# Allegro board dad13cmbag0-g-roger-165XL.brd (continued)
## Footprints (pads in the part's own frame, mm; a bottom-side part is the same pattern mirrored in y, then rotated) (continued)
BGA128-ITE-IT8528VGAX
  round 0.254 smd: A1(-3,3) A2(-2.5,3) A3(-2,3) A4(-1.5,3) A5(-1,3) A6(-0.5,3) A7(0,3) A8(0.5,3) A9(1,3) A10(1.5,3) A11(2,3) A12(2.5,3) A13(3,3) B1(-3,2.5) B2(-2.5,2.5) B3(-2,2.5) B4(-1.5,2.5) B5(-1,2.5) B6(-0.5,2.5) B7(0,2.5) B8(0.5,2.5) B9(1,2.5) B10(1.5,2.5) B11(2,2.5) B12(2.5,2.5) B13(3,2.5) C1(-3,2) C2(-2.5,2) C12(2.5,2) C13(3,2) D1(-3,1.5) D2(-2.5,1.5) D4(-1.5,1.5) D5(-1,1.5) D6(-0.5,1.5) D7(0,1.5) D8(0.5,1.5) D9(1,1.5) D10(1.5,1.5) D12(2.5,1.5) D13(3,1.5) E1(-3,1) E2(-2.5,1) E4(-1.5,1) E5(-1,1) E6(-0.5,1) E7(0,1) E8(0.5,1) E9(1,1) E10(1.5,1) E12(2.5,1) E13(3,1) F1(-3,0.5) F2(-2.5,0.5) F4(-1.5,0.5) F5(-1,0.5) F9(1,0.5) F10(1.5,0.5) F12(2.5,0.5) F13(3,0.5) G1(-3,0) G2(-2.5,0) G4(-1.5,0) G5(-1,0) G9(1,0) G10(1.5,0) G12(2.5,0) G13(3,0) H1(-3,-0.5) H2(-2.5,-0.5) H4(-1.5,-0.5) H5(-1,-0.5) H9(1,-0.5) H10(1.5,-0.5) H12(2.5,-0.5) H13(3,-0.5) J1(-3,-1) J2(-2.5,-1) J4(-1.5,-1) J5(-1,-1) J6(-0.5,-1) J7(0,-1) J8(0.5,-1) J9(1,-1) J10(1.5,-1) J12(2.5,-1) J13(3,-1) K1(-3,-1.5) K2(-2.5,-1.5) K4(-1.5,-1.5) K5(-1,-1.5) K6(-0.5,-1.5) K7(0,-1.5) K8(0.5,-1.5) K9(1,-1.5) K10(1.5,-1.5) K12(2.5,-1.5) K13(3,-1.5) L1(-3,-2) L2(-2.5,-2) L12(2.5,-2) L13(3,-2) M1(-3,-2.5) M2(-2.5,-2.5) M3(-2,-2.5) M4(-1.5,-2.5) M5(-1,-2.5) M6(-0.5,-2.5) M7(0,-2.5) M8(0.5,-2.5) M9(1,-2.5) M10(1.5,-2.5) M11(2,-2.5) M12(2.5,-2.5) M13(3,-2.5) N1(-3,-3) N2(-2.5,-3) N3(-2,-3) N4(-1.5,-3) N5(-1,-3) N6(-0.5,-3) N7(0,-3) N8(0.5,-3) N9(1,-3) N10(1.5,-3) N11(2,-3) N12(2.5,-3) N13(3,-3)
BGA1168-INTEL-HASWELL
  round 0.508 smd: A3(18.177,-11.314) A62(-18.722,-11.314) AW1(19.314,10.727) AW63(-19.314,10.743) AY2(18.771,11.314) AY62(-18.748,11.314) B2(18.806,-10.806) B63(-19.314,-10.722) C1(19.314,-10.177)
  round 0.381 smd: A4(17.421,-11.314) A5(16.76,-11.314) A6(15.564,-11.314) A59(-16.586,-11.314) A60(-17.412,-11.314) A61(-18.072,-11.314) AA9(14.282,0.262) AA21(7.627,0.175) AA23(6.199,0.175) AA58(-16.063,0.015) AB10(13.838,0.738) AB20(8.135,0.582) AB21(7.627,0.988) AB22(6.707,0.582) AB23(6.199,0.988) AB57(-15.743,0.666) AC9(14.282,1.215) AC20(8.135,1.394) AC22(6.707,1.394) AC58(-16.063,1.316) AD10(13.838,1.691) AD21(7.627,1.801) AD23(6.199,1.801) AD57(-15.743,1.966) AE9(14.282,2.167) AE10(13.838,2.643) AE20(8.135,2.207) AE21(7.627,2.614) AE22(6.707,2.207) AE23(6.199,2.614) AE58(-16.063,2.616) AF9(14.282,3.12) AF11(13.255,2.968) AF12(12.442,2.968) AF14(11.63,2.968) AF15(10.817,2.968) AF17(10.004,2.968) AF18(9.191,2.968) AF20(8.378,2.968) AF22(6.707,3.02) AG10(13.662,3.476) AG11(12.849,3.476) AG13(12.036,3.476) AG14(11.223,3.476) AG16(10.41,3.476) AG17(9.598,3.476) AG19(8.785,3.476) AG20(7.972,3.476) AG23(6.199,3.426) AG57(-15.743,3.267) AG58(-16.377,3.695) AH22(6.707,3.833) AH24(5.394,3.975) AH26(4.094,3.975) AH28(2.793,3.975) AH30(1.493,3.975) AH32(0.192,3.975) AH34(-1.108,3.975) AH36(-2.409,3.975) AH38(-3.709,3.975) AH40(-5.01,3.975) AH42(-6.31,3.975) AH44(-7.611,3.975) AH46(-8.911,3.975) AH49(-10.212,3.975) AH51(-11.512,3.975) AH53(-12.813,3.975) AH55(-14.113,3.975) AH57(-15.413,3.975) AJ23(6.199,4.239) AJ25(4.744,4.3) AJ27(3.443,4.3) AJ29(2.143,4.3) AJ31(0.843,4.3) AJ33(-0.458,4.3) AJ35(-1.758,4.3) AJ37(-3.059,4.3) AJ39(-4.359,4.3) AJ41(-5.66,4.3) AJ43(-6.96,4.3) AJ45(-8.261,4.3) AJ47(-9.561,4.3) AJ50(-10.862,4.3) AJ52(-12.162,4.3) AJ54(-13.463,4.3) AJ56(-14.763,4.3) AJ58(-16.064,4.3) AT1(19.314,8.683) AT63(-19.314,8.533) AU1(19.314,9.343) AU63(-19.314,9.359) AV1(19.314,10.004) AV2(18.654,9.993) AV62(-18.664,10.004) AV63(-19.314,10.019) AW2(18.654,10.654) AW3(17.993,10.654) AW61(-18.014,10.664) AW62(-18.664,10.664) AY3(18.047,11.314) AY4(17.387,11.314) AY5(16.726,11.314) AY59(-16.774,11.314) AY60(-17.434,11.314) AY61(-18.095,11.314) B3(18.056,-10.664) B61(-18.001,-10.654) B62(-18.664,-10.59) C2(18.664,-10.056) C62(-18.664,-9.93) C63(-19.314,-9.998) D1(19.314,-9.453) D63(-19.314,-9.338) E1(19.314,-8.792) E23(5.981,-8.713) E25(4.6,-8.713) E27(3.474,-8.713) E29(2.093,-8.713) E31(0.966,-8.713) E33(-0.415,-8.713) E35(-1.541,-8.713) E37(-2.922,-8.713) E39(-4.049,-8.713) E41(-5.43,-8.713) E43(-6.556,-8.713) E45(-7.937,-8.713) E47(-9.064,-8.713) E49(-10.444,-8.713) E51(-11.571,-8.713) E53(-12.952,-8.713) E55(-14.079,-8.713) E57(-15.459,-8.713) E63(-19.314,-8.667) F1(19.314,-7.878) F22(6.597,-8.256) F24(5.291,-8.188) F26(4.037,-8.188) F28(2.783,-8.188) F30(1.53,-8.188) F32(0.276,-8.188) F34(-0.978,-8.188) F36(-2.232,-8.188) F38(-3.485,-8.188) F40(-4.739,-8.188) F42(-5.993,-8.188) F44(-7.247,-8.188) F46(-8.5,-8.188) F48(-9.754,-8.188) F50(-11.008,-8.188) F52(-12.262,-8.188) F54(-13.515,-8.188) F56(-14.769,-8.188) F58(-16.063,-8.188) G22(6.707,-7.546) G23(5.981,-7.863) G25(4.6,-7.863) G27(3.474,-7.863) G29(2.093,-7.863) G31(0.966,-7.863) G33(-0.415,-7.863) G35(-1.541,-7.863) G37(-2.922,-7.863) G39(-4.049,-7.863) G41(-5.43,-7.863) G43(-6.556,-7.863) G45(-7.937,-7.863) G47(-9.064,-7.863) G49(-10.444,-7.863) G51(-11.571,-7.863) G53(-12.952,-7.863) G55(-14.079,-7.863) G57(-15.459,-7.863) H22(6.707,-6.734) H23(6.199,-7.14) H57(-15.743,-7.213) J22(6.707,-5.921) J23(6.199,-6.327) J58(-16.063,-6.487) K9(14.282,-5.453) K10(13.379,-5.614) K12(12.426,-5.614) K14(11.474,-5.614) K16(10.521,-5.614) K18(9.569,-5.614) K19(8.616,-5.614) K21(7.664,-5.614) K23(6.199,-5.514) K57(-15.743,-5.837) L10(13.838,-4.977) L11(12.902,-5.17) L13(11.95,-5.17) L15(10.997,-5.17) L17(10.045,-5.17) L18(9.092,-5.17) L20(8.135,-5.108) L22(6.707,-5.108) L58(-16.063,-5.186) M9(14.282,-4.5) M20(8.135,-4.295) M21(7.627,-4.702) M22(6.707,-4.295) M23(6.199,-4.702) M57(-15.743,-4.536) N10(13.838,-4.024) N21(7.627,-3.889) N23(6.199,-3.889) N58(-16.063,-3.886) P9(14.282,-3.548) P20(8.135,-3.482) P22(6.707,-3.482) P57(-15.743,-3.236) R10(13.838,-3.072) R20(8.135,-2.67) R21(7.627,-3.076) R22(6.707,-2.67) R23(6.199,-3.076) T9(14.282,-2.595) T21(7.627,-2.263) T23(6.199,-2.263) T58(-16.063,-2.585) U9(14.282,-1.643) U10(13.838,-2.119) U20(8.135,-1.857) U22(6.707,-1.857) U57(-15.743,-1.935) V10(13.838,-1.167) V21(7.627,-1.45) V23(6.199,-1.45) V58(-16.063,-1.285) W9(14.282,-0.69) W20(8.135,-1.044) W21(7.627,-0.638) W22(6.707,-1.044) W23(6.199,-0.638) W57(-15.743,-0.635) Y10(13.838,-0.214) Y20(8.135,-0.231) Y22(6.707,-0.231)
  round 0.305 smd: A8(14.776,-11.314) A9(13.862,-11.314) A11(12.948,-11.314) A12(12.198,-11.314) A14(11.284,-11.314) A15(10.37,-11.314) A17(9.62,-11.314) A18(8.706,-11.314) A20(7.791,-11.314) A21(7.042,-11.314) A23(6.128,-11.314) A24(5.291,-10.989) A25(4.6,-11.314) A27(3.474,-11.314) A28(2.783,-10.989) A29(2.093,-11.314) A31(0.966,-11.314) A32(0.276,-10.989) A33(-0.415,-11.314) A35(-1.541,-11.314) A36(-2.232,-10.989) A37(-2.922,-11.314) A39(-4.049,-11.314) A40(-4.739,-10.989) A41(-5.43,-11.314) A43(-6.556,-11.314) A44(-7.247,-10.989) A45(-7.937,-11.314) A47(-9.064,-11.314) A48(-9.754,-10.989) A49(-10.444,-11.314) A51(-11.571,-11.314) A52(-12.262,-10.989) A53(-12.952,-11.314) A55(-14.079,-11.314) A56(-14.769,-10.989) A57(-15.459,-11.314) AA1(19.314,0.402) AA2(18.664,0.402) AA3(18.014,0.364) AA4(17.363,0.364) AA59(-16.713,0.324) AA60(-17.363,0.324) AA61(-18.014,0.324) AA62(-18.664,0.362) AA63(-19.314,0.362) AB5(16.678,0.738) AB6(16.027,0.738) AB7(15.377,0.738) AB8(14.727,0.738) AC1(19.314,1.152) AC2(18.664,1.152) AC3(18.014,1.19) AC4(17.363,1.19) AC59(-16.713,1.15) AC60(-17.363,1.15) AC61(-18.014,1.15) AC62(-18.664,1.112) AC63(-19.314,1.112) AD1(19.314,1.901) AD2(18.664,1.901) AD3(18.014,1.863) AD4(17.363,1.863) AD5(16.678,1.691) AD6(16.027,1.691) AD7(15.377,1.691) AD8(14.727,1.691) AD59(-16.713,1.823) AD60(-17.363,1.823) AD61(-18.014,1.823) AD62(-18.664,1.861) AD63(-19.314,1.861) AE5(16.678,2.643) AE6(16.027,2.643) AE7(15.377,2.643) AE8(14.727,2.643) AE59(-16.713,2.648) AE60(-17.363,2.648) AE61(-18.014,2.648) AE62(-18.664,2.61) AE63(-19.314,2.61) AF1(19.314,2.65) AF2(18.664,2.65) AF3(18.014,2.688) AF4(17.363,2.688) AG1(19.314,3.4) AG2(18.664,3.4) AG3(18.014,3.361) AG4(17.363,3.361) AG5(16.678,3.596) AG6(16.027,3.596) AG7(15.377,3.596) AG8(14.727,3.596) AG21(7.359,3.807) AG60(-17.038,3.288) AG61(-17.689,3.288) AG62(-18.339,3.288) AG63(-18.989,3.288) AH1(19.314,4.149) AH2(18.664,4.149) AH3(18.014,4.187) AH4(17.363,4.187) AH10(13.662,4.162) AH11(12.849,4.162) AH13(12.036,4.162) AH14(11.223,4.162) AH16(10.41,4.162) AH17(9.598,4.162) AH19(8.785,4.162) AH20(7.972,4.162) AH60(-17.363,3.964) AH61(-18.014,3.964) AH62(-18.664,3.964) AH63(-19.314,3.964) AJ5(16.678,4.548) AJ6(16.027,4.548) AJ7(15.377,4.548) AJ8(14.727,4.548) AJ10(13.662,4.812) AJ11(12.849,4.812) AJ13(12.036,4.812) AJ14(11.223,4.812) AJ60(-17.038,4.64) AJ61(-17.689,4.64) AJ62(-18.339,4.64) AJ63(-18.989,4.64) AK1(19.314,4.898) AK2(18.664,4.898) AK3(18.014,4.86) AK4(17.363,4.86) AK8(15.011,5.137) AK18(9.466,4.952) AK20(8.513,4.952) AK21(7.561,4.952) AK60(-17.363,5.209) AK61(-18.014,5.209) AK62(-18.664,5.315) AK63(-19.314,5.315) AL1(19.314,5.647) AL2(18.664,5.647) AL3(18.014,5.686) AL4(17.363,5.686) AL5(16.413,5.462) AL7(15.575,5.462) AL8(15.011,5.787) AL10(13.657,5.462) AL11(13.093,5.787) AL13(11.738,5.462) AL15(11.174,5.787) AL17(10.092,5.268) AL18(9.466,5.602) AL20(8.513,5.602) AL21(7.561,5.602) AL22(6.608,5.602) AL23(5.786,5.602) AL25(4.81,5.602) AL26(3.858,5.602) AL28(2.905,5.602) AL29(1.953,5.602) AL31(1.054,5.277) AL32(0.49,5.602) AL33(-0.412,5.602) AL35(-1.415,5.602) AL36(-2.266,5.602) AL38(-3.32,5.602) AL39(-4.228,5.277) AL40(-4.817,5.602) AL42(-5.63,5.602) AL43(-6.582,5.602) AL45(-7.56,5.602) AL46(-8.487,5.602) AL48(-9.542,5.602) AL49(-10.443,5.602) AL51(-11.447,5.602) AL52(-12.269,5.602) AL54(-13.295,5.602) AL55(-14.248,5.602) AL57(-15.195,5.602) AL58(-16.094,5.602) AL60(-17.038,5.855) AL61(-17.689,5.855) AM1(19.314,6.397) AM2(18.664,6.397) AM3(18.014,6.359) AM4(17.363,6.359) AM5(16.413,6.112) AM7(15.575,6.112) AM8(15.011,6.437) AM10(13.657,6.112) AM11(13.093,6.437) AM13(11.738,6.112) AM15(11.174,6.437) AM17(10.092,5.919) AM18(9.466,6.252) AM20(8.513,6.252) AM21(7.561,6.252) AM22(6.608,6.252) AM23(5.786,6.252) AM25(4.81,6.252) AM26(3.858,6.252) AM28(2.905,6.252) AM29(1.953,6.252) AM31(1.054,5.927) AM32(0.49,6.252) AM33(-0.412,6.252) AM35(-1.415,6.252) AM36(-2.266,6.252) AM38(-3.32,6.252) AM40(-4.817,6.252) AM42(-5.63,6.252) AM43(-6.582,6.252) AM45(-7.56,6.252) AM46(-8.487,6.252) AM48(-9.542,6.252) AM49(-10.443,6.252) AM51(-11.447,6.252) AM52(-12.269,6.252) AM54(-13.295,6.252) AM55(-14.248,6.252) AM57(-15.195,6.252) AM58(-16.094,6.252) AM60(-17.363,6.501) AM61(-18.014,6.501) AM62(-18.664,6.395) AM63(-19.314,6.395) AN1(19.314,7.146) AN2(18.664,7.146) AN3(18.014,7.184) AN4(17.363,7.184) AN5(16.413,6.762) AN7(15.575,6.762) AN8(15.011,7.088) AN10(13.657,6.762) AN11(13.093,7.088) AN13(11.738,6.762) AN15(11.174,7.088) AN17(10.092,6.569) AN18(9.466,6.903) AN20(8.513,6.903) AN21(7.561,6.903) AN22(6.608,6.903) AN23(5.786,6.903) AN25(4.81,6.903) AN26(3.858,6.903) AN28(2.905,6.903) AN29(1.953,6.903) AN31(1.054,6.578) AN32(0.49,6.903) AN33(-0.412,6.903) AN35(-1.415,6.903) AN36(-2.266,6.903) AN38(-3.32,6.903) AN39(-4.228,6.578) AN40(-4.817,6.903) AN42(-5.63,6.903) AN43(-6.582,6.903) AN45(-7.56,6.903) AN46(-8.487,6.903) AN48(-9.542,6.903) AN49(-10.443,6.903) AN51(-11.447,6.903) AN52(-12.269,6.903) AN54(-13.295,6.903) AN55(-14.248,6.903) AN57(-15.195,6.903) AN58(-16.094,6.903) AN60(-17.038,7.07) AN61(-17.689,7.07) AN62(-18.339,7.07) AN63(-18.989,7.07) AP1(19.314,7.895) AP2(18.664,7.895) AP3(18.014,7.857) AP4(17.363,7.857) AP5(16.413,7.413) AP7(15.575,7.413) AP8(15.011,7.738) AP10(13.657,7.413) AP11(13.093,7.738) AP13(11.738,7.413) AP15(11.174,7.738) AP17(10.092,7.219) AP18(9.466,7.553) AP20(8.513,7.553) AP21(7.561,7.553) AP22(6.608,7.553) AP23(5.786,7.553) AP25(4.81,7.553) AP26(3.858,7.553) AP28(2.905,7.553) AP29(1.953,7.553) AP31(1.054,7.228) AP32(0.49,7.553) AP33(-0.412,7.553) AP35(-1.415,7.553) AP36(-2.266,7.553) AP38(-3.32,7.553) AP39(-4.228,7.228) AP40(-4.817,7.553) AP42(-5.63,7.553) AP43(-6.582,7.553) AP45(-7.56,7.553) AP46(-8.487,7.553) AP48(-9.542,7.553) AP49(-10.443,7.553) AP51(-11.447,7.553) AP52(-12.269,7.553) AP54(-13.295,7.553) AP55(-14.248,7.553) AP57(-15.195,7.553) AP58(-16.094,7.553) AP60(-17.363,7.746) AP61(-18.014,7.746) AP62(-18.664,7.746) AP63(-19.314,7.746) AR5(16.413,8.063) AR7(15.575,8.063) AR8(15.011,8.388) AR10(13.657,8.063) AR11(13.093,8.388) AR13(11.738,8.063) AR15(11.174,8.388) AR17(10.092,7.869) AR18(9.466,8.203) AR20(8.513,8.203) AR21(7.561,8.203) AR22(6.608,8.203) AR23(5.786,8.203) AR25(4.81,8.203) AR26(3.858,8.203) AR28(2.905,8.203) AR29(1.953,8.203) AR31(1.054,7.878) AR32(0.49,8.203) AR33(-0.412,8.203) AR35(-1.415,8.203) AR36(-2.266,8.203) AR38(-3.32,8.203) AR39(-4.228,7.878) AR40(-4.817,8.203) AR42(-5.63,8.203) AR43(-6.582,8.203) AR45(-7.56,8.203) AR46(-8.487,8.203) AR48(-9.542,8.203) AR49(-10.443,8.203) AR51(-11.447,8.203) AR52(-12.269,8.203) AR54(-13.295,8.203) AR55(-14.248,8.203) AR57(-15.195,8.203) AR58(-16.094,8.203) AT2(18.664,8.645) AT3(18.014,8.683) AT4(17.363,8.683) AT5(16.413,8.713) AT7(15.575,8.713) AT10(13.657,8.713) AT13(11.738,8.713) AT35(-1.122,8.905) AT37(-2.697,8.905) AT40(-4.272,8.905) AT42(-5.847,8.905) AT43(-7.422,8.905) AT46(-8.996,8.905) AT49(-10.597,8.933) AT61(-17.689,8.32) AT62(-18.498,8.376) AU2(18.659,9.333) AU3(17.999,9.333) AU4(17.338,9.333) AU6(15.977,9.363) AU7(15.151,9.363) AU8(14.478,9.363) AU10(13.653,9.363) AU11(12.98,9.363) AU12(12.154,9.363) AU14(11.481,9.363) AU15(10.656,9.363) AU16(10.092,9.038) AU17(9.454,9.363) AU18(8.778,9.038) AU19(8.21,9.363) AU20(7.563,9.038) AU21(6.917,9.363) AU22(6.348,9.038) AU23(5.672,9.363) AU24(4.996,9.038) AU25(4.321,9.363) AU26(3.645,9.038) AU27(3.076,9.363) AU28(2.43,9.038) AU29(1.783,9.363) AU30(1.214,9.038) AU31(0.539,9.363) AU33(-0.058,9.016) AU34(-0.66,9.363) AU35(-1.585,9.363) AU36(-2.235,9.363) AU37(-3.16,9.363) AU39(-3.81,9.363) AU40(-4.734,9.363) AU41(-5.385,9.363) AU42(-6.309,9.363) AU43(-6.959,9.363) AU44(-7.884,9.363) AU46(-8.534,9.363) AU47(-9.459,9.363) AU49(-10.109,9.363) AU50(-11.086,9.363) AU51(-11.666,9.038) AU52(-12.342,9.363) AU53(-13.017,9.038) AU54(-13.586,9.363) AU55(-14.233,9.038) AU56(-14.879,9.363) AU57(-15.448,9.038) AU58(-16.124,9.363) AU59(-16.688,9.038) AU60(-17.251,9.363) AU61(-17.963,9.087) AU62(-18.664,9.349) AV3(17.993,9.993) AV4(17.338,9.993) AV5(16.65,10.014) AV6(15.977,10.014) AV7(15.151,10.014) AV8(14.478,10.014) AV10(13.653,10.014) AV11(12.98,10.014) AV12(12.154,10.014) AV14(11.481,10.014) AV15(10.656,10.014) AV16(10.092,9.689) AV17(9.454,10.014) AV18(8.778,9.689) AV19(8.21,10.014) AV20(7.563,9.689) AV21(6.917,10.014) AV22(6.348,9.689) AV23(5.672,10.014) AV24(4.996,9.689) AV25(4.321,10.014) AV26(3.645,9.689) AV27(3.076,10.014) AV28(2.43,9.689) AV29(1.783,10.014) AV30(1.214,9.689) AV31(0.539,10.014) AV33(-0.086,9.689) AV34(-0.71,10.014) AV35(-1.535,10.014) AV36(-2.284,10.014) AV37(-3.11,10.014) AV39(-3.859,10.014) AV40(-4.685,10.014) AV41(-5.434,10.014) AV42(-6.26,10.014) AV43(-7.009,10.014) AV44(-7.834,10.014) AV46(-8.584,10.014) AV47(-9.409,10.014) AV49(-10.158,10.014) AV50(-10.984,10.014) AV51(-11.666,9.689) AV52(-12.342,10.014) AV53(-13.017,9.689) AV54(-13.586,10.014) AV55(-14.233,9.689) AV56(-14.879,10.014) AV57(-15.448,9.689) AV58(-16.124,10.014) AV59(-16.688,9.689) AV60(-17.251,10.014) AV61(-17.988,9.737) AW4(17.338,10.654) AW5(16.688,10.664) AW6(15.939,10.664) AW7(15.189,10.664) AW8(14.44,10.664) AW10(13.691,10.664) AW11(12.942,10.664) AW12(12.192,10.664) AW14(11.443,10.664) AW15(10.694,10.664) AW16(10.092,10.339) AW17(9.454,10.664) AW18(8.778,10.339) AW19(8.103,10.664) AW21(7.023,10.664) AW22(6.348,10.339) AW23(5.672,10.664) AW24(4.996,10.339) AW25(4.321,10.664) AW26(3.645,10.339) AW27(2.97,10.664) AW29(1.89,10.664) AW30(1.214,10.339) AW31(0.539,10.664) AW33(-0.137,10.339) AW34(-0.71,10.664) AW35(-1.535,10.664) AW36(-2.284,10.664) AW37(-3.11,10.664) AW39(-3.859,10.664) AW40(-4.685,10.664) AW41(-5.434,10.664) AW42(-6.26,10.664) AW43(-7.009,10.664) AW44(-7.834,10.664) AW46(-8.584,10.664) AW47(-9.409,10.664) AW49(-10.158,10.664) AW50(-10.984,10.664) AW51(-11.666,10.339) AW52(-12.342,10.664) AW53(-13.017,10.339) AW54(-13.693,10.664) AW56(-14.772,10.664) AW57(-15.448,10.339) AW58(-16.124,10.664) AW59(-16.688,10.339) AW60(-17.251,10.664) AY6(15.939,11.314) AY7(15.189,11.314) AY8(14.44,11.314) AY10(13.691,11.314) AY11(12.942,11.314) AY12(12.192,11.314) AY14(11.443,11.314) AY15(10.694,11.314) AY16(10.13,10.989) AY17(9.454,11.314) AY18(8.778,10.989) AY19(8.103,11.314) AY21(7.023,11.314) AY22(6.348,10.989) AY23(5.672,11.314) AY24(4.996,10.989) AY25(4.321,11.314) AY26(3.645,10.989) AY27(2.97,11.314) AY29(1.89,11.314) AY30(1.214,10.989) AY31(0.539,11.314) AY33(-0.137,10.989) AY34(-0.71,11.314) AY35(-1.535,11.314) AY36(-2.284,11.314) AY37(-3.11,11.314) AY39(-3.859,11.314) AY40(-4.685,11.314) AY41(-5.434,11.314) AY42(-6.26,11.314) AY43(-7.009,11.314) AY44(-7.834,11.314) AY46(-8.584,11.314) AY47(-9.409,11.314) AY49(-10.158,11.314) AY50(-10.984,11.314) AY51(-11.666,10.989) AY52(-12.342,11.314) AY53(-13.017,10.989) AY54(-13.693,11.314) AY56(-14.772,11.314) AY57(-15.448,10.989) AY58(-16.124,11.314) B4(17.393,-10.664) B5(16.176,-10.672) B6(15.196,-10.672) B8(14.423,-10.672) B9(13.598,-10.672) B11(12.617,-10.672) B12(11.845,-10.672) B14(11.02,-10.672) B15(10.039,-10.672) B17(9.267,-10.672) B18(8.442,-10.672) B20(7.461,-10.672) B21(7.042,-10.118) B22(6.689,-10.672) B23(5.864,-10.672) B24(5.291,-10.339) B25(4.6,-10.664) B26(4.037,-10.339) B27(3.474,-10.664) B28(2.783,-10.339) B29(2.093,-10.664) B30(1.53,-10.339) B31(0.966,-10.664) B32(0.276,-10.339) B33(-0.415,-10.664) B34(-0.978,-10.339) B35(-1.541,-10.664) B36(-2.232,-10.339) B37(-2.922,-10.664) B38(-3.485,-10.339) B39(-4.049,-10.664) B40(-4.739,-10.339) B41(-5.43,-10.664) B42(-5.993,-10.339) B43(-6.556,-10.664) B44(-7.247,-10.339) B45(-7.937,-10.664) B46(-8.5,-10.339) B47(-9.064,-10.664) B48(-9.754,-10.339) B49(-10.444,-10.664) B50(-11.008,-10.339) B51(-11.571,-10.664) B52(-12.262,-10.339) B53(-12.952,-10.664) B54(-13.515,-10.339) B55(-14.079,-10.664) B56(-14.769,-10.339) B57(-15.459,-10.664) B58(-16.023,-10.339) B59(-16.586,-10.664) B60(-17.351,-10.654) C3(18.012,-10.012) C4(17.196,-10.042) C5(16.542,-10.118) C6(15.538,-10.118) C8(14.776,-10.118) C9(13.964,-10.118) C11(12.96,-10.118) C12(12.198,-10.118) C14(11.386,-10.118) C15(10.382,-10.118) C17(9.62,-10.118) C18(8.807,-10.118) C20(7.804,-10.118) C21(7.423,-9.529) C22(6.636,-9.529) C23(6.229,-10.118) C24(5.263,-9.282) C25(4.6,-10.014) C26(4.037,-9.689) C27(3.474,-10.014) C28(2.756,-9.282) C29(2.093,-10.014) C30(1.53,-9.689) C31(0.966,-10.014) C32(0.248,-9.282) C33(-0.415,-10.014) C34(-0.978,-9.689) C35(-1.541,-10.014) C36(-2.259,-9.282) C37(-2.922,-10.014) C38(-3.485,-9.689) C39(-4.049,-10.014) C40(-4.767,-9.282) C41(-5.43,-10.014) C42(-5.993,-9.689) C43(-6.556,-10.014) C44(-7.274,-9.282) C45(-7.937,-10.014) C46(-8.5,-9.689) C47(-9.064,-10.014) C48(-9.756,-9.282) C49(-10.444,-10.014) C50(-11.008,-9.689) C51(-11.571,-10.014) C52(-12.264,-9.323) C53(-12.952,-10.014) C54(-13.515,-9.689) C55(-14.079,-10.014) C56(-14.771,-9.323) C57(-15.459,-10.014) C58(-16.023,-9.689) C59(-16.586,-10.014) C61(-17.689,-10.077) D2(18.664,-9.24) D3(18.014,-9.278) D5(16.636,-9.472) D6(15.945,-9.529) D8(15.157,-9.529) D9(14.37,-9.529) D11(13.462,-9.529) D12(12.579,-9.529) D14(11.792,-9.529) D15(10.884,-9.529) D17(10.001,-9.529) D18(9.214,-9.529) D20(8.306,-9.529) D21(7.079,-8.891) D23(5.937,-9.529) D25(4.6,-9.363) D26(4.037,-9.038) D27(3.474,-9.363) D29(2.093,-9.363) D30(1.53,-9.038) D31(0.966,-9.363) D33(-0.415,-9.363) D34(-0.978,-9.038) D35(-1.541,-9.363) D37(-2.922,-9.363) D38(-3.485,-9.038) D39(-4.049,-9.363) D41(-5.43,-9.363) D42(-5.993,-9.038) D43(-6.556,-9.363) D45(-7.937,-9.363) D46(-8.5,-9.038) D47(-9.064,-9.363) D49(-10.444,-9.363) D50(-11.008,-9.038) D51(-11.571,-9.363) D53(-12.952,-9.363) D54(-13.515,-9.038) D55(-14.079,-9.363) D57(-15.459,-9.363) D58(-16.023,-9.038) D59(-16.586,-9.363) D60(-17.363,-9.513) D61(-18.014,-9.513) D62(-18.664,-9.28) E2(18.664,-8.589) E3(18.014,-8.627) E4(17.363,-8.627) E5(16.712,-8.695) E6(15.76,-8.695) E8(14.807,-8.695) E10(13.855,-8.695) E11(12.902,-8.695) E13(11.95,-8.695) E15(10.997,-8.695) E17(10.045,-8.695) E18(9.092,-8.695) E20(8.14,-8.695) E59(-16.713,-8.667) E60(-17.363,-8.667) E61(-18.014,-8.667) E62(-18.664,-8.629) F2(18.664,-7.84) F3(18.014,-7.802) F4(17.363,-7.802) F5(16.712,-8.045) F6(15.76,-8.045) F8(14.807,-8.045) F10(13.855,-8.045) F11(12.902,-8.045) F13(11.95,-8.045) F15(10.997,-8.045) F17(10.045,-8.045) F18(9.092,-8.045) F20(8.14,-8.045) F59(-16.713,-7.842) F60(-17.363,-7.842) F61(-18.014,-7.842) F62(-18.664,-7.88) F63(-19.314,-7.88) G1(19.314,-7.091) G2(18.664,-7.091) G3(18.014,-7.129) G4(17.363,-7.129) G5(16.712,-7.395) G6(15.76,-7.395) G8(14.807,-7.395) G10(13.855,-7.395) G11(12.902,-7.395) G13(11.95,-7.395) G15(10.997,-7.395) G17(10.045,-7.395) G18(9.092,-7.395) G20(8.14,-7.395) H5(16.712,-6.745) H6(15.76,-6.745) H8(14.807,-6.745) H10(13.855,-6.745) H11(12.902,-6.745) H13(11.95,-6.745) H15(10.997,-6.745) H17(10.045,-6.745) H18(9.092,-6.745) H20(8.14,-6.745) H59(-16.713,-7.169) H60(-17.363,-7.169) H61(-18.014,-7.169) H62(-18.664,-7.131) H63(-19.314,-7.131) J1(19.314,-6.341) J2(18.664,-6.341) J3(18.014,-6.303) J4(17.363,-6.303) J5(16.687,-6.094) J6(15.747,-6.094) J8(14.807,-6.094) J10(13.855,-6.094) J11(12.902,-6.094) J13(11.95,-6.094) J15(10.997,-6.094) J17(10.045,-6.094) J18(9.092,-6.094) J20(8.14,-6.094) J21(7.219,-6.328) J59(-16.713,-6.343) J60(-17.363,-6.343) J61(-18.014,-6.343) J62(-18.664,-6.381) J63(-19.314,-6.381) K1(19.314,-5.592) K2(18.664,-5.592) K3(18.014,-5.63) K4(17.363,-5.63) K59(-16.713,-5.67) K60(-17.363,-5.67) K61(-18.014,-5.67) K62(-18.664,-5.632) K63(-19.314,-5.632) L1(19.314,-4.843) L2(18.664,-4.843) L3(18.014,-4.805) L4(17.363,-4.805) L5(16.678,-4.977) L6(16.027,-4.977) L7(15.377,-4.977) L8(14.727,-4.977) L59(-16.713,-4.845) L60(-17.363,-4.845) L61(-18.014,-4.845) L62(-18.664,-4.883) L63(-19.314,-4.883) N1(19.314,-4.093) N2(18.664,-4.093) N3(18.014,-4.132) N4(17.363,-4.132) N5(16.678,-4.024) N6(16.027,-4.024) N7(15.377,-4.024) N8(14.727,-4.024) N59(-16.713,-4.172) N60(-17.363,-4.172) N61(-18.014,-4.172) N62(-18.664,-4.134) N63(-19.314,-4.134) P1(19.314,-3.344) P2(18.664,-3.344) P3(18.014,-3.306) P4(17.363,-3.306) P59(-16.713,-3.346) P60(-17.363,-3.346) P61(-18.014,-3.346) P62(-18.664,-3.384) P63(-19.314,-3.384) R5(16.678,-3.072) R6(16.027,-3.072) R7(15.377,-3.072) R8(14.727,-3.072) T1(19.314,-2.595) T2(18.664,-2.595) T3(18.014,-2.633) T4(17.363,-2.633) T59(-16.713,-2.673) T60(-17.363,-2.673) T61(-18.014,-2.673) T62(-18.664,-2.635) T63(-19.314,-2.635) U1(19.314,-1.846) U2(18.664,-1.846) U3(18.014,-1.807) U4(17.363,-1.807) U5(16.678,-2.119) U6(16.027,-2.119) U7(15.377,-2.119) U8(14.727,-2.119) U59(-16.713,-1.848) U60(-17.363,-1.848) U61(-18.014,-1.848) U62(-18.664,-1.886) U63(-19.314,-1.886) V1(19.314,-1.096) V2(18.664,-1.096) V3(18.014,-1.134) V4(17.363,-1.134) V5(16.678,-1.167) V6(16.027,-1.167) V7(15.377,-1.167) V8(14.727,-1.167) V59(-16.713,-1.174) V60(-17.363,-1.174) V61(-18.014,-1.174) V62(-18.664,-1.136) V63(-19.314,-1.136) Y1(19.314,-0.347) Y2(18.664,-0.347) Y3(18.014,-0.309) Y4(17.363,-0.309) Y5(16.678,-0.214) Y6(16.027,-0.214) Y7(15.377,-0.214) Y8(14.727,-0.214) Y59(-16.713,-0.349) Y60(-17.363,-0.349) Y61(-18.014,-0.349) Y62(-18.664,-0.387) Y63(-19.314,-0.387)
  round 0.33 smd: AK22(6.659,4.952) AK23(5.786,4.952) AK25(4.81,4.952) AK26(3.858,4.952) AK28(2.905,4.952) AK29(2.004,4.952) AK32(0.49,4.952) AK33(-0.412,4.952) AK35(-1.415,4.952) AK36(-2.266,4.952) AK38(-3.295,4.952) AK40(-4.792,4.952) AK42(-5.63,4.952) AK43(-6.582,4.952) AK45(-7.56,4.952) AK46(-8.462,4.952) AK48(-9.516,4.952) AK49(-10.418,4.952) AK51(-11.421,4.952) AK52(-12.269,4.952) AK54(-13.295,4.952) AK55(-14.248,4.952) AK57(-15.195,4.952) AK58(-16.094,4.952)
CC3_5X1_7
  rect 1.803x1.905 smd: 1(-1.7,0) 2(1.7,0)
CC0201
  rect 0.203x0.381 smd: 1(-0.225,0) 2(0.225,0)
CC0402
  custom 0.12x0.12 smd: 1(0.39,0) 2(-0.39,0)
CC0603
  rect 0.813x0.711 smd: 1(0.737,0) 2(-0.737,0)
CC0805
  rect 0.94x1.346 smd: 1(0.895,0) 2(-0.895,0)
CC3216-0_9H
  rect 1.651x1.092 smd: 1(-1.225,0) 2(1.225,0)
CC3528
  rect 2.032x2.413 smd: 1(1.6,0) 2(-1.6,0)
CC7343
  rect 2.413x2.819 smd: 1(-3.2,0) 2(3.2,0)
CHOKE-A915AY-H-100M
  rect 0.991x2.007 smd rot 45: 1(-1.768,1.768) 2(1.768,-1.768)
CHOKE-DLP11SN900HL2L-4P-1
  rect 0.305x0.711 smd: 1(-0.275,-0.625) 2(-0.275,0.625) 3(0.275,0.625) 4(0.275,-0.625)
CHOKE-MPLC0730L3R3
  rect 2.007x3.505 smd: 1(-2.95,0) 2(2.95,0)
CHOKE-PCMB053T-1R0MS
  rect 2.007x2.489 smd: 1(-2.5,0) 2(2.5,0)
CHOKE-PCMC063T-R82MN-4P-SMT
  custom 0.591x0.591 smd: 1(-3.596,0) 2(3.596,0)
  rect 1.473x0.305 smd: 3(-2.452,0) 4(2.452,0)
D-SOD-123FL-2_8X1_8
  rect 1.194x1.194 smd: 1(-1.525,0) 2(1.525,0)
DFN10-3X3-5-11P-RT9296
  rect 0.305x0.991 smd: 1(-1,-1.6) 2(-0.5,-1.6) 3(0,-1.6) 4(0.5,-1.6) 5(1,-1.6) 6(1,1.6) 7(0.5,1.6) 8(0,1.6) 9(-0.5,1.6) 10(-1,1.6)
  rect 2.464x1.626 smd: 11(0,0)
DP-3V112M1-RC5AA1-7H-20P
  round 0.787 hole 0.508: 1(-2.7,3.3) 3(-2.1,4.5) 5(-1.6,3.3) 7(-1,4.5) 9(-0.5,3.3) 11(0.5,3.3) 13(1,4.5) 15(1.6,3.3) 17(2.1,4.5) 19(2.7,3.3)
  rect 0.406x2.21 smd: 2(-2.7,6.4) 4(-2.1,6.4) 6(-1.5,6.4) 8(-0.9,6.4) 10(-0.3,6.4) 12(0.3,6.4) 14(0.9,6.4) 16(1.5,6.4) 18(2.1,6.4) 20(2.7,6.4)
  oval 1.041x2.438 hole 0.559x1.956: 21(-5,5.15) 22(5,5.15)
  oval 1.194x2.311 hole 0.711x1.803: 23(-5.1,0) 24(5.1,0)
  oval 1.194x2.489 hole 0.711x2.007: 25(-5.1,-6.25) 26(5.1,-6.25)
DSMV
  rect 0.762x1.016 smd: 1(0,1.27) 2(0,-1.27)
F-3_2X1_65-3_68
  rect 2.159x1.397 smd: 1(-1.84,0) 2(1.84,0)
FSMD1206P150TS
  rect 1.016x1.803 smd: 1(-1.725,0) 2(1.725,0)
GS12401-1011-40P-R-NH-SMT
  round 0.94 hole 0.94 unplated: (-10.5,0) (10.5,0)
  rect 0.254x1.143 smd: 1(9.75,2.125) 2(9.25,2.125) 3(8.75,2.125) 4(8.25,2.125) 5(7.75,2.125) 6(7.25,2.125) 7(6.75,2.125) 8(6.25,2.125) 9(5.75,2.125) 10(5.25,2.125) 11(4.75,2.125) 12(4.25,2.125) 13(3.75,2.125) 14(3.25,2.125) 15(2.75,2.125) 16(2.25,2.125) 17(1.75,2.125) 18(1.25,2.125) 19(0.75,2.125) 20(0.25,2.125) 21(-0.25,2.125) 22(-0.75,2.125) 23(-1.25,2.125) 24(-1.75,2.125) 25(-2.25,2.125) 26(-2.75,2.125) 27(-3.25,2.125) 28(-3.75,2.125) 29(-4.25,2.125) 30(-4.75,2.125) 31(-5.25,2.125) 32(-5.75,2.125) 33(-6.25,2.125) 34(-6.75,2.125) 35(-7.25,2.125) 36(-7.75,2.125) 37(-8.25,2.125) 38(-8.75,2.125) 39(-9.25,2.125) 40(-9.75,2.125)
  rect 1.499x2.997 smd: 41(12.65,0) 42(-12.65,0)
  rect 2.794x1.499 smd: 43(5.7,-2.45) 44(-5.7,-2.45)
GS73091-10272-7H-9P-LUV_AB
  rect 2.489x2.997 smd: 1(-8.5,-4.775) 2(8.5,-4.775)
  rect 0.66x1.448 smd: A1(-6,1.45) A2(-4.5,1.45) A3(-3,1.45) A4(-1.5,1.45) A5(0,1.45) A6(1.5,1.45) A7(3,1.45) A8(4.5,1.45) A9(6,1.45)
  rect 0.66x2.743 smd: B1(-6,-1.45) B2(-4.5,-1.45) B3(-3,-1.45) B4(-1.5,-1.45) B5(0,-1.45) B6(1.5,-1.45) B7(3,-1.45) B8(4.5,-1.45) B9(6,-1.45)
H-C79D79N
  round 2.007 hole 2.007 unplated: (0,0)
H-C217IC142D102PT
  round 2.591 hole 2.591: 1(0,0)
H-C220D142P2
  round 5.588 hole 3.607: 1(0,0)
H-O79X87D79X87N
  oval 2.007x2.21 hole 2.007x2.21 unplated: (0,0)
H-TC166BC177IC131D91P2
  round 4.216 hole 2.311: 1(0,0)
H-TC197BC220IC131D91P2
  round 5.004 hole 2.311: 1(0,0)
H-TC217BC197D102P2
  round 5.004 hole 2.591: 1(0,0)
H-TC217BC197IC142D102P2
  round 5.004 hole 2.591: 1(0,0)
H-TC217IC142BC197D102P2
  round 5.004 hole 2.591: 1(0,0)
H-TIC217BC220D91P2
  round 5.512 hole 2.311: 1(0,0)
L3_2X2_5-1_55
  rect 1.245x2.007 smd: 1(-1.275,0) 2(1.275,0)
LEDLTW-270TLA
  rect 0.711x0.711 smd: 1(-0.7,0) 2(0.7,0)
MINIPCI-SM3ZS067U215AE-75P-KE
  round 1.092 hole 1.092 unplated: (-10,0)
  round 1.6 hole 1.6 unplated: (10,0)
  rect 0.305x1.549 smd: 1(-9.25,5.225) 2(-9,-2.225) 3(-8.75,5.225) 4(-8.5,-2.225) 5(-8.25,5.225) 6(-8,-2.225) 7(-7.75,5.225) 8(-7.5,-2.225) 9(-7.25,5.225) 10(-7,-2.225) 11(-6.75,5.225) 12(-6.5,-2.225) 13(-6.25,5.225) 14(-6,-2.225) 15(-5.75,5.225) 16(-5.5,-2.225) 17(-5.25,5.225) 18(-5,-2.225) 19(-4.75,5.225) 20(-4.5,-2.225) 21(-4.25,5.225) 22(-4,-2.225) 23(-3.75,5.225) 32(-1.5,-2.225) 33(-1.25,5.225) 34(-1,-2.225) 35(-0.75,5.225) 36(-0.5,-2.225) 37(-0.25,5.225) 38(0,-2.225) 39(0.25,5.225) 40(0.5,-2.225) 41(0.75,5.225) 42(1,-2.225) 43(1.25,5.225) 44(1.5,-2.225) 45(1.75,5.225) 46(2,-2.225) 47(2.25,5.225) 48(2.5,-2.225) 49(2.75,5.225) 50(3,-2.225) 51(3.25,5.225) 52(3.5,-2.225) 53(3.75,5.225) 54(4,-2.225) 55(4.25,5.225) 56(4.5,-2.225) 57(4.75,5.225) 58(5,-2.225) 59(5.25,5.225) 60(5.5,-2.225) 61(5.75,5.225) 62(6,-2.225) 63(6.25,5.225) 64(6.5,-2.225) 65(6.75,5.225) 66(7,-2.225) 67(7.25,5.225) 68(7.5,-2.225) 69(7.75,5.225) 70(8,-2.225) 71(8.25,5.225) 72(8.5,-2.225) 73(8.75,5.225) 74(9,-2.225) 75(9.25,5.225)
  rect 1.194x2.743 smd: 76(-10.35,4.5) 77(10.35,4.5)
MIPCI-800055FB052GX00PL-52P-SMT
  round 1.6 hole 1.6 unplated: (-12.5,0)
  round 1.092 hole 1.092 unplated: (12.5,0)
  rect 0.508x2.007 smd: 1(-11.8,-4.1) 2(-11.4,4.1) 3(-11,-4.1) 4(-10.6,4.1) 5(-10.2,-4.1) 6(-9.8,4.1) 7(-9.4,-4.1) 8(-9,4.1) 9(-8.6,-4.1) 10(-8.2,4.1) 11(-7.8,-4.1) 12(-7.4,4.1) 13(-7,-4.1) 14(-6.6,4.1) 15(-6.2,-4.1) 16(-5.8,4.1) 17(-2.2,-4.1) 18(-1.8,4.1) 19(-1.4,-4.1) 20(-1,4.1) 21(-0.6,-4.1) 22(-0.2,4.1) 23(0.2,-4.1) 24(0.6,4.1) 25(1,-4.1) 26(1.4,4.1) 27(1.8,-4.1) 28(2.2,4.1) 29(2.6,-4.1) 30(3,4.1) 31(3.4,-4.1) 32(3.8,4.1) 33(4.2,-4.1) 34(4.6,4.1) 35(5,-4.1) 36(5.4,4.1) 37(5.8,-4.1) 38(6.2,4.1) 39(6.6,-4.1) 40(7,4.1) 41(7.4,-4.1) 42(7.8,4.1) 43(8.2,-4.1) 44(8.6,4.1) 45(9,-4.1) 46(9.4,4.1) 47(9.8,-4.1) 48(10.2,4.1) 49(10.6,-4.1) 50(11,4.1) 51(11.4,-4.1) 52(11.8,4.1)
  rect 2.311x3.2 smd: 53(-14.65,-3.5) 54(14.65,-3.5)
PAD-M14-1
  custom 2.5x2.5 smd: 1(-8.128,-4.572)
PG-TSDSON-8-8P-R
  rect 0.33x0.787 smd: 1(0.975,1.5) 2(0.325,1.5) 3(-0.325,1.5) 4(-0.975,1.5)
  custom 0.573x0.573 smd: 5(0,-0.72)
  rect 0.33x0.66 smd: 6(-0.325,-1.575) 7(0.325,-1.575) 8(0.975,-1.575)
PVQFN20-3_5X3_5-5-25P
  rect 0.279x0.838 smd: 1(-1,-1.725) 2(-0.5,-1.725) 3(0,-1.725) 4(0.5,-1.725) 5(1,-1.725) 11(1,1.725) 12(0.5,1.725) 13(0,1.725) 14(-0.5,1.725) 15(-1,1.725)
  rect 0.838x0.279 smd: 6(1.725,-1) 7(1.725,-0.5) 8(1.725,0) 9(1.725,0.5) 10(1.725,1) 16(-1.725,1) 17(-1.725,0.5) 18(-1.725,0) 19(-1.725,-0.5) 20(-1.725,-1)
  rect 2.057x2.057 smd: 21(0,0)
  round 0.61 hole 0.305: 22(-0.5,-0.5) 23(0.5,-0.5) 24(0.5,0.5) 25(-0.5,0.5)
QFN16-3X3-5-17P-TPS2546RTER
  rect 0.991x0.305 smd: 1(-1.6,0.75) 2(-1.6,0.25) 3(-1.6,-0.25) 4(-1.6,-0.75) 9(1.6,-0.75) 10(1.6,-0.25) 11(1.6,0.25) 12(1.6,0.75)
  rect 0.305x0.991 smd: 5(-0.75,-1.6) 6(-0.25,-1.6) 7(0.25,-1.6) 8(0.75,-1.6) 13(0.75,1.6) 14(0.25,1.6) 15(-0.25,1.6) 16(-0.75,1.6)
  rect 1.702x1.702 smd: 17(0,0)
QFN24-4X4-5-25P-0_8H
  rect 0.991x0.305 smd: 1(-2.1,1.25) 2(-2.1,0.75) 3(-2.1,0.25) 4(-2.1,-0.25) 5(-2.1,-0.75) 6(-2.1,-1.25) 13(2.1,-1.25) 14(2.1,-0.75) 15(2.1,-0.25) 16(2.1,0.25) 17(2.1,0.75) 18(2.1,1.25)
  rect 0.305x0.991 smd: 7(-1.25,-2.1) 8(-0.75,-2.1) 9(-0.25,-2.1) 10(0.25,-2.1) 11(0.75,-2.1) 12(1.25,-2.1) 19(1.25,2.1) 20(0.75,2.1) 21(0.25,2.1) 22(-0.25,2.1) 23(-0.75,2.1) 24(-1.25,2.1)
  rect 2.007x2.007 smd: 25(0,0)
QFN28-4_5X3_5-4-29P
  rect 0.203x0.991 smd: 1(-1.6,-1.85) 2(-1.2,-1.85) 3(-0.8,-1.85) 4(-0.4,-1.85) 5(0,-1.85) 6(0.4,-1.85) 7(0.8,-1.85) 8(1.2,-1.85) 9(1.6,-1.85) 15(1.6,1.85) 16(1.2,1.85) 17(0.8,1.85) 18(0.4,1.85) 19(0,1.85) 20(-0.4,1.85) 21(-0.8,1.85) 22(-1.2,1.85) 23(-1.6,1.85)
  rect 0.991x0.203 smd: 10(2.35,-0.8) 11(2.35,-0.4) 12(2.35,0) 13(2.35,0.4) 14(2.35,0.8) 24(-2.35,0.8) 25(-2.35,0.4) 26(-2.35,0) 27(-2.35,-0.4) 28(-2.35,-0.8)
  rect 3.099x2.108 smd: 29(0,0)
QFN32-4X4-4-42P-1H
  custom 0.05x0.05 smd: 1(-2,1.4) 2(-2,1) 3(-2,0.6) 4(-2,0.2) 5(-2,-0.2) 6(-2,-0.6) 7(-2,-1) 8(-2,-1.4) 9(-1.4,-2) 10(-1,-2) 11(-0.6,-2) 12(-0.2,-2) 13(0.2,-2) 14(0.6,-2) 15(1,-2) 16(1.4,-2) 17(2,-1.4) 18(2,-1) 19(2,-0.6) 20(2,-0.2) 21(2,0.2) 22(2,0.6) 23(2,1) 24(2,1.4) 25(1.4,2) 26(1,2) 27(0.6,2) 28(0.2,2) 29(-0.2,2) 30(-0.6,2) 31(-1,2) 32(-1.4,2)
  rect 2.794x2.794 smd: 33(0,0)
  round 0.61 hole 0.305: 34(-1,1) 35(-1,0) 36(-1,-1) 37(0,-1) 38(1,-1) 39(1,0) 40(1,1) 41(0,1) 42(0,0)
QFN48-7X7-5-49P-ALC5505-CG
  rect 0.305x0.991 smd: 1(-2.75,-3.6) 2(-2.25,-3.6) 3(-1.75,-3.6) 4(-1.25,-3.6) 5(-0.75,-3.6) 6(-0.25,-3.6) 7(0.25,-3.6) 8(0.75,-3.6) 9(1.25,-3.6) 10(1.75,-3.6) 11(2.25,-3.6) 12(2.75,-3.6) 25(2.75,3.6) 26(2.25,3.6) 27(1.75,3.6) 28(1.25,3.6) 29(0.75,3.6) 30(0.25,3.6) 31(-0.25,3.6) 32(-0.75,3.6) 33(-1.25,3.6) 34(-1.75,3.6) 35(-2.25,3.6) 36(-2.75,3.6)
  rect 0.991x0.305 smd: 13(3.6,-2.75) 14(3.6,-2.25) 15(3.6,-1.75) 16(3.6,-1.25) 17(3.6,-0.75) 18(3.6,-0.25) 19(3.6,0.25) 20(3.6,0.75) 21(3.6,1.25) 22(3.6,1.75) 23(3.6,2.25) 24(3.6,2.75) 37(-3.6,2.75) 38(-3.6,2.25) 39(-3.6,1.75) 40(-3.6,1.25) 41(-3.6,0.75) 42(-3.6,0.25) 43(-3.6,-0.25) 44(-3.6,-0.75) 45(-3.6,-1.25) 46(-3.6,-1.75) 47(-3.6,-2.25) 48(-3.6,-2.75)
  rect 5.461x5.461 smd: 49(0,0)
RC0402
  custom 0.12x0.12 smd: 1(0.39,0) 2(-0.39,0)
RC0603
  rect 0.813x0.711 smd: 1(0.737,0) 2(-0.737,0)
RC0805
  rect 0.94x1.346 smd: 1(0.895,0) 2(-0.895,0)
RC1206
  rect 1.6x1.6 smd: 1(1.702,0) 2(-1.702,0)
RC3216-4P
  custom 0.235x0.235 smd: 1(0,1.168) 2(0,-1.168)
  rect 1.092x0.559 smd: 1P(0,0.634) 2P(0,-0.634)
SHORT0201
  rect 0.343x0.381 smd: 1(-0.225,0) 2(0.225,0)
SHORT0402
  rect 0.648x0.5 smd: 1(-0.39,0) 2(0.39,0)
SHORT0603
  rect 1.219x0.711 smd: 1(0.737,0) 2(-0.737,0)
SHORT0805
  rect 1.397x1.346 smd: 1(0.895,0) 2(-0.895,0)
SHORT1206
  rect 2.527x1.6 smd: 1(1.702,0) 2(-1.702,0)
SOIC8-7_9-1_27-2_16H
  rect 0.533x1.549 smd: 1(-1.905,-3.775) 2(-0.635,-3.775) 3(0.635,-3.775) 4(1.905,-3.775) 5(1.905,3.775) 6(0.635,3.775) 7(-0.635,3.775) 8(-1.905,3.775)
SON8-2X2-5-9P
  rect 0.279x0.508 smd: 1(-0.75,-0.95) 2(-0.25,-0.95) 3(0.25,-0.95) 4(0.75,-0.95) 5(0.75,0.95) 6(0.25,0.95) 7(-0.25,0.95) 8(-0.75,0.95)
  rect 1.6x0.889 smd: 9(0,0)
SON8-4_5X3_5-5-9P
  custom 0.05x0.05 smd: 1(-1.6,-1.6) 2(-1.2,-1.6) 3(-0.8,-1.6) 6(-0.8,1.6) 7(-1.2,1.6) 8(-1.6,1.6)
  custom 0.15x0.15 smd: 4(0.6,-1.6) 5(0.6,1.6)
  rect 4.039x2.21 smd: 9(0,0)
SON14-3X2-4-15P
  custom 0.05x0.05 smd: 1(-1.2,-1.025) 2(-0.8,-1.025) 3(-0.4,-1.025) 4(0,-1.025) 5(0.4,-1.025) 6(0.8,-1.025) 7(1.2,-1.025) 8(1.2,1.025) 9(0.8,1.025) 10(0.4,1.025) 11(0,1.025) 12(-0.4,1.025) 13(-0.8,1.025) 14(-1.2,1.025)
  rect 2.489x0.889 smd: 15(0,0)
SOT23-5
  rect 1.016x0.711 smd: 1(1.2,-0.95) 2(1.2,0) 3(1.2,0.95) 4(-1.2,0.95) 5(-1.2,-0.95)
SOT23_123-2_37-1_9-1_11H
  rect 0.787x0.889 smd: 1(0.95,1) 2(-0.95,1) 3(0,-1)
SOT23_213-3_3-2
  rect 1.27x1.016 smd: 1(1.016,1.016) 2(1.016,-1.016) 3(-1.016,0)
SOT353-1-2_125-65-5P
  rect 1.245x0.279 smd: 1(1.045,-0.65) 2(1.045,0) 3(1.045,0.65) 4(-1.045,0.65) 5(-1.045,-0.65)
SOT363-2_1-65-6P
  rect 0.889x0.356 smd: 1(0.8,-0.65) 2(0.8,0) 3(0.8,0.65) 4(-0.8,0.65) 5(-0.8,0) 6(-0.8,-0.65)
SOT-363
  rect 1.219x0.254 smd: 1(1.038,-0.65) 2(1.038,0) 3(1.038,0.65) 4(-1.038,0.65) 5(-1.038,0) 6(-1.038,-0.65)
SPAD-RE95X87
  rect 2.413x2.21 smd: 1(0,0)
SSOP5-P-A-TOSHIBA-B
  rect 0.305x1.067 smd: 1(0.65,0.85) 2(0,0.85) 3(-0.65,0.85) 4(-0.65,-0.85) 5(0.65,-0.85)
SSOT6-2_8-95
  rect 0.991x0.686 smd: 1(1.295,-0.95) 2(1.295,0) 3(1.295,0.95) 4(-1.295,0.95) 5(-1.295,0) 6(-1.295,-0.95)
SW-SKRELJE010-2P-SMT
  round 0.813 hole 0.813 unplated: (0,0.9) (0,-0.9)
  rect 0.889x1.702 smd: 1(-2.05,0) 2(2.05,0)
TP2650
  round 0.66 smd: 1(0,0)
TSOP6-2_8-95
  rect 0.787x0.635 smd: 1(1.2,-0.95) 2(1.2,0) 3(1.2,0.95) 4(-1.2,0.95) 5(-1.2,0) 6(-1.2,-0.95)
TSOT23-6-2_8-95-6P-1H
  rect 0.508x1.194 smd: 1(-0.95,-1.5) 2(0,-1.5) 3(0.95,-1.5) 4(0.95,1.5) 5(0,1.5) 6(-0.95,1.5)
TSSOP8-6_4-65
  rect 0.305x1.499 smd: 1(-0.975,-3.05) 2(-0.325,-3.05) 3(0.325,-3.05) 4(0.975,-3.05) 5(0.975,3.05) 6(0.325,3.05) 7(-0.325,3.05) 8(-0.975,3.05)
TSSOP10-4_9-5
  rect 0.279x1.499 smd: 1(-1,-2.3) 2(-0.5,-2.3) 3(0,-2.3) 4(0.5,-2.3) 5(1,-2.3) 6(1,2.3) 7(0.5,2.3) 8(0,2.3) 9(-0.5,2.3) 10(-1,2.3)
TSSOP28-6_4-65-1_2H
  rect 0.305x1.499 smd: 1(-4.225,-3.05) 2(-3.575,-3.05) 3(-2.925,-3.05) 4(-2.275,-3.05) 5(-1.625,-3.05) 6(-0.975,-3.05) 7(-0.325,-3.05) 8(0.325,-3.05) 9(0.975,-3.05) 10(1.625,-3.05) 11(2.275,-3.05) 12(2.925,-3.05) 13(3.575,-3.05) 14(4.225,-3.05) 15(4.225,3.05) 16(3.575,3.05) 17(2.925,3.05) 18(2.275,3.05) 19(1.625,3.05) 20(0.975,3.05) 21(0.325,3.05) 22(-0.325,3.05) 23(-0.975,3.05) 24(-1.625,3.05) 25(-2.275,3.05) 26(-2.925,3.05) 27(-3.575,3.05) 28(-4.225,3.05)
UDFN10-2_5X1-5
  rect 0.254x0.508 smd: 1(-1,-0.4) 2(-0.5,-0.4) 4(0.5,-0.4) 5(1,-0.4) 6(1,0.4) 7(0.5,0.4) 9(-0.5,0.4) 10(-1,0.4)
  rect 0.457x0.508 smd: 3(0,-0.4) 8(0,0.4)
UMT_213-3-1_3
  rect 1.016x0.762 smd: 1(0.991,0.66) 2(0.991,-0.66) 3(-0.991,0)
unnamed#2
  round 1.016 smd: 1(0,0)
UQFN12-2X1_7-4
  custom 0.1x0.1 smd: 1(-0.8,-0.65)
  rect 0.203x0.61 smd: 2(-0.4,-0.65) 3(0,-0.65) 4(0.4,-0.65) 5(0.8,-0.65) 7(0.8,0.65) 8(0.4,0.65) 9(0,0.65) 10(-0.4,0.65) 11(-0.8,0.65)
  rect 0.61x0.203 smd: 6(0.8,0) 12(-0.8,0)
USB-YUSB0011-P001A-10P
  round 1.194 hole 0.787: 1(3.5,7.55) 2(1,7.55) 3(-1,7.55) 5(-4.5,8.85) 6(-2.25,8.85) 7(0,8.85) 8(2.25,8.85) 9(4.5,8.85)
  round 1.041 hole 0.787: 4(-3.5,7.55)
  round 0.965 hole 0.762: 10(-4.7,7.58)
  oval 1.626x2.921 hole 0.61x1.905: 11(7.9,0) 12(-7.9,0) 13(7.4,8.76) 14(-7.4,8.76)
VSSOP8-3_1-5-8P-0_9H
  rect 0.305x0.787 smd: 1(-0.75,-1.55) 2(-0.25,-1.55) 3(0.25,-1.55) 4(0.75,-1.55) 5(0.75,1.55) 6(0.25,1.55) 7(-0.25,1.55) 8(-0.75,1.55)
WQFN20-3X3-4-21P
  rect 0.991x0.203 smd: 1(-1.6,0.8) 2(-1.6,0.4) 3(-1.6,0) 4(-1.6,-0.4) 5(-1.6,-0.8) 11(1.6,-0.8) 12(1.6,-0.4) 13(1.6,0) 14(1.6,0.4) 15(1.6,0.8)
  rect 0.203x0.991 smd: 6(-0.8,-1.6) 7(-0.4,-1.6) 8(0,-1.6) 9(0.4,-1.6) 10(0.8,-1.6) 16(0.8,1.6) 17(0.4,1.6) 18(0,1.6) 19(-0.4,1.6) 20(-0.8,1.6)
  rect 1.702x1.702 smd: 21(0,0)
XTAL-8_4X3_7-5_5X2_8
  rect 1.295x2.057 smd: 1(-2.75,-1.425) 2(2.75,-1.425) 3(2.75,1.425) 4(-2.75,1.425)
XTL-3_2X2_5-2_2X1_7-0_8H
  rect 1.397x1.194 smd: 1(-1.1,-0.85) 2(1.1,-0.85) 3(1.1,0.85) 4(-1.1,0.85)
YEA-BTB-055-P01-54P-LDH-SMT
  round 0.66 hole 0.66 unplated: (-7.55,1.5) (7.55,-1.5)
  rect 0.305x1.6 smd: 1(-6.5,-1.8) 2(-6,-1.8) 3(-5.5,-1.8) 4(-5,-1.8) 5(-4.5,-1.8) 6(-4,-1.8) 7(-3.5,-1.8) 8(-3,-1.8) 9(-2.5,-1.8) 10(-2,-1.8) 11(-1.5,-1.8) 12(-1,-1.8) 13(-0.5,-1.8) 14(0,-1.8) 15(0.5,-1.8) 16(1,-1.8) 17(1.5,-1.8) 18(2,-1.8) 19(2.5,-1.8) 20(3,-1.8) 21(3.5,-1.8) 22(4,-1.8) 23(4.5,-1.8) 24(5,-1.8) 25(5.5,-1.8) 26(6,-1.8) 27(6.5,-1.8) 28(6.5,1.8) 29(6,1.8) 30(5.5,1.8) 31(5,1.8) 32(4.5,1.8) 33(4,1.8) 34(3.5,1.8) 35(3,1.8) 36(2.5,1.8) 37(2,1.8) 38(1.5,1.8) 39(1,1.8) 40(0.5,1.8) 41(0,1.8) 42(-0.5,1.8) 43(-1,1.8) 44(-1.5,1.8) 45(-2,1.8) 46(-2.5,1.8) 47(-3,1.8) 48(-3.5,1.8) 49(-4,1.8) 50(-4.5,1.8) 51(-5,1.8) 52(-5.5,1.8) 53(-6,1.8) 54(-6.5,1.8)
  rect 0.787x1.803 smd: 55(-8.25,0) 56(8.25,0)

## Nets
1.35V_SUS_PWRGD: PU10.10 R26.1
3.3V_ALW_ON: Q4.3 R42.2 R67.2
+0.675V_DDR_VTT: C178.1 C182.1 C183.1 C188.1 C189.1 C192.1 C193.1 C194.1 C195.1 C197.1 C198.1 C199.1 C200.1 C201.1 C202.1 C203.1 C204.1 C205.1 C206.1 C209.1 C526.1 C527.1 PR91.1 R225.2 R228.2 R230.1 R233.2 R234.2 R235.1 R236.1 R239.1 R411.1 R412.1 R413.1 R414.1 R415.1 R416.1 R417.1 R418.1 R419.1 R420.1 R421.1 R422.1 R423.1 R424.1 R425.1 R426.1 R427.1 R428.1 R429.1 R430.1 R431.1 R432.1 R433.1 R434.1 R435.1 R436.1 R437.1 R438.1 R439.1 R440.1 R441.1 R442.1 R443.1 R444.1 R445.1 R446.1 R447.1 R448.1 R449.1 R450.1 R451.1 R452.1 R453.1 R454.1 R455.1 R456.1 R457.1 R458.1
+1.2V_SWR: C134.1 C135.1 C139.1 C142.1 C144.1 C148.1 C160.1 C164.1 C165.1 C166.1 L3.2 Q19.3 U10.1 U10.15 U10.25 U10.37
+1.2V_SWR_L: L3.1 U10.13
+1.5V_RUN: PC74.1 PC75.1 PC79.1 PR101.1 PU11.1 R62.2
+1.05V_RUN: C18.2 C19.1 C48.1 C49.1 C68.1 C96.1 C103.2 C104.1 C105.2 L8.1 L9.1 L10.1 PC6.1 PC9.1 PU2.8 PU2.9 PU2.13 PU2.14 R1.2 R95.1 U16.AE8 U16.AE9 U16.AF9 U16.AF22 U16.AG8 U16.AG13 U16.AG14 U16.AG16 U16.AG17 U16.H11 U16.H15 U16.J11 U16.J17 U16.N8 U16.P9 U16.R21 U16.T21
+1.05V_SUS: C91.1 C121.2 C122.2 C123.2 L11.1 PC14.1 PC26.1 PC34.1 PC136.1 PC137.1 PC138.1 PC139.1 PC140.1 PC142.1 PL1.2 PQ9.5 PQ9.6 PQ9.7 PQ9.8 PR158.2 PU2.1 PU2.2 PU2.6 PU2.7 R132.1 R133.1 R134.1 R135.2 U16.AD8 U16.AD10 U16.AH13 U16.J13
+1.8V_RUN: PC176.1 PU19.7 PU19.8 R64.2 R159.1 R162.1 R170.1 R172.1 R173.2 R181.1 R184.2 R186.2 R192.2 R336.2 R337.2 R338.2 R339.2 R340.2 R341.2
+1.8V_SUS: PC62.1 PC180.1 PC210.1 PC214.1 PC215.1 PC216.1 PL8.1 PR215.1 PU11.3 PU19.1 PU19.2 Q32.2 R370.1
+3.3V_ALW: C3.1 C4.1 C5.1 C6.1 CN6.2 EC25.1 ESD2.5 PC17.1 PC20.1 PC36.1 PC37.1 PC65.1 PC77.1 PC88.1 PC99.1 PC100.1 PC125.1 PC181.1 PC198.1 PC199.1 PC205.1 PL6.1 PR133.2 PR134.1 PR142.1 PR148.1 PR208.1 PU3.1 PU3.2 PU3.6 PU3.7 PU5.1 PU5.2 PU5.6 PU5.7 PU9.1 PU9.2 PU9.6 PU9.7 PU13.6 PU13.7 PU14.1 PU14.2 PU14.6 PU14.7 PU16.6 PU16.7 PU20.1 R6.2 R15.1 R21.1 R39.1 R47.2 R72.1 R73.1 R89.1 R123.1 R165.1 R223.1 R471.1 RP1.2 RP1.4 RP2.2 RP2.4 RT1.1 SJ2.1
+3.3V_ALW_AVCC: C45.1 L2.1 U4.E9
+3.3V_DEEP_SLEEP_OFF: C78.1 C85.2 CN3.27 EC62.1 Q9.3 Q13.2 Q18.2 Q28.2 Q28.5 R48.1 R100.2 R107.2 R108.2 R113.2 R116.2 R119.2 R124.2 R127.2 R141.2 R143.2 R144.2 R156.2 R177.2 R317.2 R322.2 R323.2 R325.2 R326.2 R328.2 R342.2 R347.2 R350.2 R369.1 RP6.2 RP6.4 RP7.2 RP7.4 RP8.2 RP8.4 U16.AA9 U16.AC9 U16.AE20 U16.AE21 U16.AH11
+3.3V_DSW: C119.2 R123.2 R128.2 U16.AH10
+3.3V_EC: L2.2 Q29.2 R15.2 R344.1 U4.D4 U4.D5 U4.D10 U4.E4 U4.K4 U4.K10
+3.3V_EN2: PQ7.2 R67.1 R75.1
+3.3V_RTC_LDO: D18.1 PC70.2 PR26.1 PU7.15 Q30.3 R41.1 R42.1 R472.1 R475.1
+3.3V_RUN: C44.1 C140.1 DPF1.1 PC10.1 PC35.1 PR27.2 PR47.1 PU3.8 PU3.9 PU4.1 PU4.2 PU18.20 PU18.21 R12.1 R13.1 R28.2 R44.1 R60.2 R63.2 R65.2 R68.2 R78.2 R81.1 R82.1 R84.2 R85.2 R86.2 R87.2 R91.2 R92.2 R93.2 R94.2 R98.2 R176.2 R185.2 R220.1 R265.2 R266.1 R267.2 R269.2 R270.2 R273.1 R276.2 R277.2 R278.1 R280.2 R281.2 R286.2 R291.2 R292.2 R295.2 R302.2 R305.2 R345.1 R459.1 R477.2 RP3.2 RP3.4 RP4.2 RP4.4 RP5.2 RP5.4 RP26.2 RP26.4 RP27.1 RP27.3 RP29.1 RP29.3 RP30.2 RP30.4 RP31.2 RP31.4 RP31.6 RP31.8 RP33.2 RP33.4 RP34.2 RP34.4 RP35.2 RP35.4 RP36.2 RP36.4 U1.5 U4.J5 U5.4 U5.5 U9.5 U13.11
+3.3V_RUN_DPF1: C245.1 C246.2 CN1.20 DPF1.2
+3.3V_RUN_ON_P: PC29.1 PR42.1 PR230.2 PU3.5
+3.3V_SUS: C525.1 PC16.1 PU3.13 PU3.14 Q9.1 R90.2 R114.2 R115.2 R128.1 R130.1 R131.2 R146.2 R177.1 R182.1 R285.1 R297.1 R312.1 R318.2 R332.2 R348.2 R349.2 R473.1 R476.2
+3.3V_SUS_ON_P: PC27.1 PR40.2 PR41.1 PU3.3
+3.3V_THERMAL: C126.1 PR127.2 Q16.2 Q16.5 R136.1 R137.1 R220.2 RP14.1 RP14.3 U8.1
+3.3V_TPM: C41.2 C42.1 C94.2 C95.1 C100.2 C101.1 PR46.2 U6.5 U6.10 U6.19 U6.24
+5V_ALW: C97.2 C107.2 CN3.1 CN3.2 CN3.3 CN3.4 CN3.5 CN6.1 EC26.1 EC63.1 EC64.1 EC66.1 ESD1.5 ESD3.5 PC22.1 PC23.1 PC43.1 PC46.1 PC78.1 PC91.1 PC98.1 PC109.1 PC119.1 PC124.1 PC129.1 PC186.1 PC189.1 PC211.1 PC217.1 PD2.2 PL5.2 PQ5.1 PQ5.2 PQ5.5 PQ5.6 PR56.1 PR82.2 PR83.1 PR168.1 PU2.4 PU4.4 PU5.4 PU9.4 PU13.4 PU14.4 PU15.1 PU15.2 PU15.6 PU15.7 PU16.1 PU16.2 PU16.4 PU21.8 PU21.9 PU21.10 R106.1 R125.1 R129.1 R147.2 R206.1 R217.1 R229.1 R241.1 R243.1 SJ3.1 SJ4.1 U7.1
+5V_ALW2: PC28.1 PC76.2 PC113.1 PD6.1 PR31.1 PR136.1 PR222.1 PU3.4 PU7.13 PU7.14 PU15.4 R407.1 R409.1 RTCR1.1
+5V_FAN: CN3.50 EC56.1 PR129.2 R226.2
+5V_FAN_R: PC116.1 PR129.1 PU16.13 PU16.14
+5V_PTC: PC38.1 PC40.1 PC42.1 PC53.1 PC197.1 PC201.1 PQ5.4 PR56.2 PR72.1 PR74.1 PR218.1 PR219.1 PU6.5 PU8.8 PU20.5
+5V_RUN: C54.1 C63.1 C274.1 FS1.1 PC13.1 PC71.1 PC103.1 PC120.1 PQ19.2 PR19.2 PU11.5 PU13.1 PU13.2 PU15.8 PU15.9 Q1.2 Q15.1 R9.2 R22.2 R111.2 R164.2 R226.1 U2.8 U3.8
+5V_RUN_ON_P: PC115.1 PR125.1 PR128.2 PU15.5
+5V_SUS: PC104.1 PC178.1 PU15.13 PU15.14 PU19.4
+5V_SUS_ON_P: PC111.1 PR120.2 PR123.1 PU15.3
+15V_ALW: PC44.1 PD3.1 PD7.1 PQ4.1 PR37.1 PR44.1 PR63.1
+DVDD-25-LDO-O: C141.1 C143.1 C157.1 PR103.1 U10.43
+V1.05A_AOSCSUS: C80.1 C81.1 C86.2 L11.2 U16.AB8
+V1.05DX_MODPHY: C58.2 C60.2 C64.2 L6.1 L7.1 PQ9.1 PQ9.2 PQ9.3 PR39.1 U16.K9 U16.L10 U16.M9
+V1.05S_APLLOPI: C62.1 C66.1 C112.1 L8.2 U16.AA21 U16.W21
+V1.05S_ASATA3PLL: C236.1 C238.1 C239.1 L7.2 R254.2 R263.2 U16.B11
+V1.05S_AUSB3PLL: C11.1 C12.1 C17.1 L6.2 R25.1 R27.1 U16.B18
+V1.05S_AXCK_DCB: C47.1 C50.1 C51.1 L10.2 U16.J18 U16.K19
+V1.05S_AXCK_LCPLL: C1.1 C2.1 C40.1 L9.2 R35.2 U16.A20
+V1.05S_VCCST: PR188.2 PR191.1 R45.2 R95.2 R253.1 R261.1 R282.1 R289.1 R293.1 U16.AC22 U16.AE22 U16.AE23
+V3.3_THERMAL_R: PC121.1 PR127.1 PU16.8 PU16.9
+V3.3DX_1.5DX_AUDIO: C120.2 R130.2 R462.2 U16.AH14
+V3.3DX_ALS: C71.1 J1.6 Q26.2 Q26.5 Q27.2 Q27.5 R201.2 RP32.1 RP32.3
+V3.3DX_ALS_R: PC106.1 PU14.13 PU14.14 R201.1
+V3.3DX_AUDIO: C146.1 C150.1 C151.1 C152.1 C154.1 C155.1 CN3.26 PR107.2 Q24.2 Q24.5 R169.1 R462.1 R463.2 R465.1 RP9.2 RP9.4 U10.14 U10.16 U10.42 U11.11
+V3.3DX_AUDIO_IO: CN3.25 EC65.1 R465.2 R473.2
+V3.3DX_CAMERA: C77.1 J1.7 J1.8 PR34.2
+V3.3DX_CAMERA_R: PC30.1 PR34.1 PU5.8 PU5.9
+V3.3DX_NGFF_WLAN: C145.1 C149.1 C153.1 C278.1 C279.1 CN4.2 CN4.4 CN4.72 CN4.74 PR65.2 R200.2 R212.2 R215.2 R216.2 R484.1 R485.1 R486.1
+V3.3DX_NGFF_WLAN_R: PC52.1 PR65.1 PU9.8 PU9.9
+V3.3DX_SSD: C14.1 C147.1 C258.1 CON1.2 CON1.24 CON1.39 CON1.41 CON1.52 PR76.2 R474.2
+V3.3DX_SSD_R: PC49.1 PR76.1 PU9.13 PU9.14
+V3.3DX_TCH_PAD: C275.1 C277.1 JP1.1 Q25.2 Q25.5 Q36.2 R214.2 R395.1 RP10.1 RP10.3 RP11.1 RP11.3
+V3.3DX_TCH_PAD_R: PC108.1 PU14.8 PU14.9 R214.1
+V3.3DX_TCH_SCR: C281.1 JP2.2 PR35.2 R59.1
+V3.3DX_TCH_SCR_R: PC31.1 PR35.1 PU5.13 PU5.14
+V3.3S_1.8S_LPSS_SDIO: C61.1 R60.1 R64.1 R272.1 U16.T9 U16.U8
+V5DX_AUDIO: CN3.51 CN3.52 CN3.53 CN3.54 EC57.1 EC58.1 PR117.2
+VCCIN: C21.1 C22.1 C23.1 C24.1 C25.1 C26.1 C27.1 C28.1 C29.1 C30.1 C31.1 C32.1 C33.1 C34.1 C35.1 C36.1 C37.1 C38.1 C46.1 C52.1 C57.1 C59.1 C65.1 C70.1 C76.1 C84.1 C87.1 C92.1 C98.1 C110.1 PC166.1 PC167.1 PC168.1 PC169.1 PC171.1 PC172.1 PC173.1 PC174.1 PC175.1 PL3.2 R32.2 R408.1 U16.AB57 U16.AD57 U16.AG57 U16.C24 U16.C28 U16.C32 U16.C36 U16.C40 U16.C44 U16.C48 U16.C52 U16.C56 U16.E23 U16.E25 U16.E27 U16.E29 U16.E31 U16.E33 U16.E35 U16.E37 U16.E39 U16.E41 U16.E43 U16.E45 U16.E47 U16.E49 U16.E51 U16.E53 U16.E55 U16.E57 U16.F24 U16.F28 U16.F32 U16.F36 U16.F40 U16.F44 U16.F48 U16.F52 U16.F56 U16.F59 U16.G23 U16.G25 U16.G27 U16.G29 U16.G31 U16.G33 U16.G35 U16.G37 U16.G39 U16.G41 U16.G43 U16.G45 U16.G47 U16.G49 U16.G51 U16.G53 U16.G55 U16.G57 U16.H23 U16.J23 U16.K23 U16.K57 U16.L22 U16.M23 U16.M57 U16.P57 U16.U57 U16.W57
+VCCIO_OUT: R283.1 R288.1 R290.1 U16.A59
+VCCIOA_OUT: R40.2 U16.E20
AGND_LB: PC1.2 PC3.2 PC4.2 PC5.2 PC147.2 PR1.2 PR6.2 PR9.2 PR10.2 PR12.2 PR16.2 PR156.1 PR161.2 PU1.5
